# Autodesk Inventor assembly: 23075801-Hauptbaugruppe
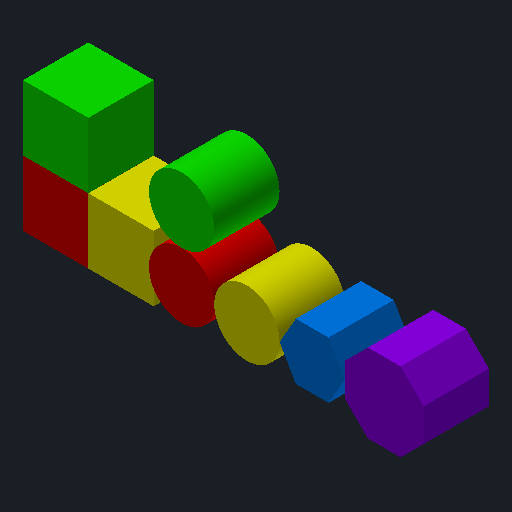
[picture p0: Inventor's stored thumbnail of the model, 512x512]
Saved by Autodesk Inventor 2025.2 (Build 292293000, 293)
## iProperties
Company: Ed. Züblin AG
Created: 2025-03
Part Number: 23075801-Hauptbaugruppe
Material: Stahlbeton C30/37
Document SubType Name: Assembly
Designer: FrodlSte
Mass: 1.80321e+07 g
Surface Area: 428504 cm^2
Volume: 7.21282e+06 cm^3
Density: 2.5 g/cm^3
Description: VKL K-4A.1
z_Bereich: Tunnelbau
z_Direktion: Tief- und Tunnelbau
z_Konzerneinheit: Zentrale Technik
cpiComponentType: Attribut
cpiFitMatchkey: =<z_Matchkey>
z_Matchkey: =<z_Matchkey_010>_<z_Matchkey_020>_<z_Matchkey_030>_<z_Matchkey_040>_<z_Matchkey_050>_<z_Matchkey_060>_<z_Matchkey_070>_<z_Matchkey_080>_<z_Matchkey_090>_<z_Mat
z_Matchkey_010: xxxxx
z_Matchkey_020: 5DTUB
z_Matchkey_030: xxx
z_Matchkey_040: xxx
z_Matchkey_050: xxx
z_Matchkey_060: xxx
z_Matchkey_070: xxx
z_Matchkey_080: xxx
z_Matchkey_090: xxx
z_Matchkey_100: xxx
z_Matchkey_110: xxx
z_Matchkey_120: xxxxxxx
z_Matchkey_130: xxxx
z_Matchkey_140: xxxx
DocNumber: 23075801-Hauptbaugruppe.iam
Folder: DL23075801-DE-Pfaffensteigtunnel\BIM\Testmodell
VDS_Category: 09 - BIM - Konstruktion
DBSet_TU_Ausbruch:Vortriebsklasse: VKL K-4A.1
DBSet_TU_Drainage_Ausbruch:Vortriebsklasse: VKL K-4A.1
DBSet_TU_Aussenschale:Vortriebsklasse: VKL K-4A.1
z_DBSet_TU_Ausbruch:Vortriebsklasse: Vortriebsklasse K-4A.1
z_DBSet_TU_Drainage_Ausbruch:Vortriebsklasse: Vortriebsklasse K-4A.1
z_DBSet_TU_Aussenschale:Vortriebsklasse: Vortriebsklasse K-4A.1
Author: FrodlSte
Title: Vortriebsklasse K-4A.1
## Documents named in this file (5)
- C:\z_Vault\CAD\DL23075801-DE-Pfaffensteigtunnel\BIM\Testmodell\23075801-Hauptbaugruppe.iam
- C:\z_Vault\CAD\DL23075801-DE-Pfaffensteigtunnel\BIM\Testmodell\23075801-Sechseck.ipt
- C:\z_Vault\CAD\DL23075801-DE-Pfaffensteigtunnel\BIM\Testmodell\23075801-Achteck.ipt
- C:\z_Vault\CAD\DL23075801-DE-Pfaffensteigtunnel\BIM\Testmodell\23075801-Baugruppe_Quadrate.iam
- C:\z_Vault\CAD\DL23075801-DE-Pfaffensteigtunnel\BIM\Testmodell\23075801-Baugruppe_Kreise.iam
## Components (4 placed, 4 different names)
1. 23075801-Sechseck:1
2. 23075801-Achteck:1
3. 23075801-Baugruppe_Quadrate:1 [sub-assembly]
4. 23075801-Baugruppe_Kreise:1 [sub-assembly]
